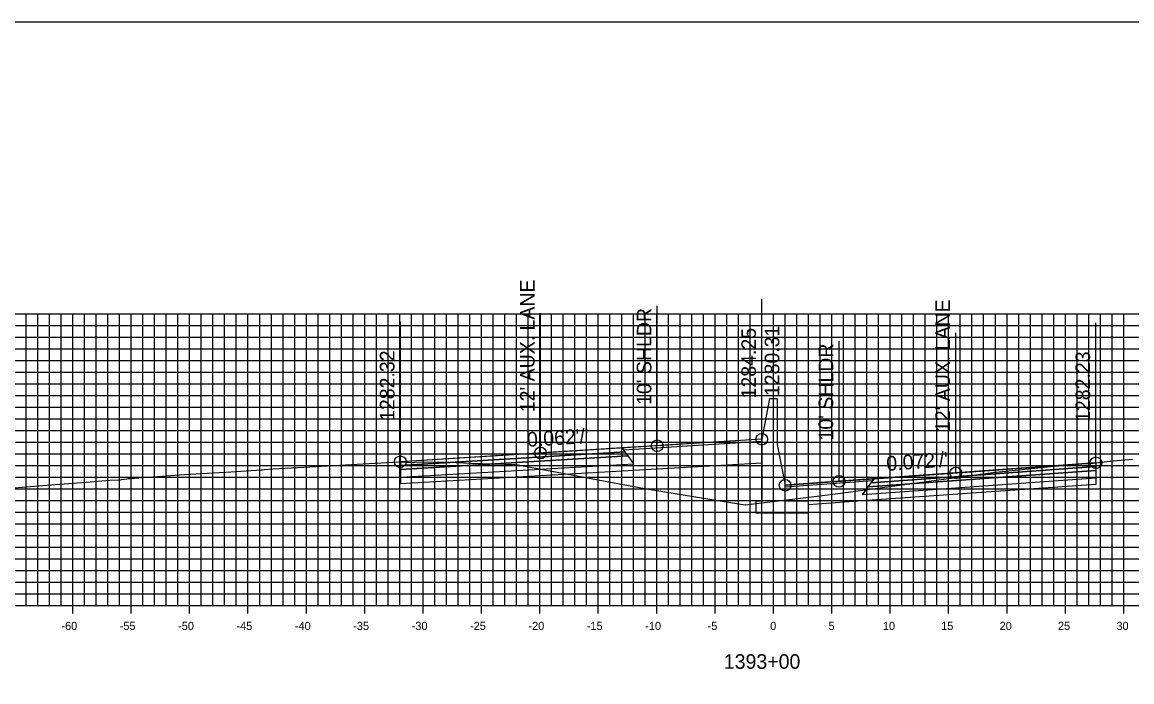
# Model space of a CAD drawing. Extents: x 674939 to 678919, y 750652 to 765176.
# Drawn here: x 678674.2 to 678769.2, y 755916 to 755972.6 of the extents above; entities that cross this region are included whole.
import ezdxf

# ---------------------------------------------------------------- set-up
doc = ezdxf.new("R2010")
doc.units = 0
for name, color, linetype in [('R_Alt Surface', 7, 'Continuous'), ('R_Axis', 7, 'Continuous'), ('R_Axis Annot', 7, 'Continuous'), ('R_Exist Surface', 7, 'Continuous'), ('R_Fin Surface', 7, 'Continuous'), ('R_Grid', 7, 'Continuous'), ('R_No Plot', 7, 'Continuous'), ('R_Proposed Road', 7, 'Continuous'), ('R_Xsect Elev', 7, 'Continuous'), ('R_Xsect Slope', 7, 'Continuous')]:
    doc.layers.add(name, color=color, linetype=linetype)

msp = doc.modelspace()

# ---------------------------------------------------------------- linework, layer by layer
at = {"layer": 'R_Alt Surface'}
for points in [[(678706.579, 755934.541), (678706.579, 755934.211), (678726.079, 755935.375), (678725.829, 755935.715)], [(678706.579, 755934.211), (678706.579, 755933.551), (678726.579, 755934.695), (678726.079, 755935.375)], [(678766.148, 755934.453), (678766.148, 755934.123), (678746.648, 755932.73), (678746.898, 755933.07)], [(678766.148, 755934.123), (678766.148, 755933.463), (678746.148, 755932.05), (678746.648, 755932.73)]]:
    msp.add_lwpolyline(points, close=True, dxfattribs=at)
for points in [[(678726.579, 755934.155), (678737.533, 755934.781)], [(678706.579, 755933.551), (678706.579, 755933.011), (678726.579, 755934.155)], [(678766.148, 755933.463), (678766.149, 755932.923), (678746.148, 755931.51)], [(678746.148, 755931.51), (678741.533, 755931.184)]]:
    msp.add_lwpolyline(points, dxfattribs=at)
at = {"layer": 'R_Axis'}
for p, q in [((678678.533, 755921.851), (678678.533, 755923.251)), ((678683.533, 755921.851), (678683.533, 755923.251)), ((678688.533, 755921.851), (678688.533, 755923.251)), ((678693.533, 755921.851), (678693.533, 755923.251)), ((678698.533, 755921.851), (678698.533, 755923.251)), ((678703.533, 755921.851), (678703.533, 755923.251)), ((678708.533, 755921.851), (678708.533, 755923.251)), ((678713.533, 755921.851), (678713.533, 755923.251)), ((678718.533, 755921.851), (678718.533, 755923.251)), ((678723.533, 755921.851), (678723.533, 755923.251)), ((678728.533, 755921.851), (678728.533, 755923.251)), ((678733.533, 755921.851), (678733.533, 755923.251)), ((678738.533, 755921.851), (678738.533, 755923.251)), ((678743.533, 755921.851), (678743.533, 755923.251)), ((678748.533, 755921.851), (678748.533, 755923.251)), ((678753.533, 755921.851), (678753.533, 755923.251)), ((678758.533, 755921.851), (678758.533, 755923.251)), ((678763.533, 755921.851), (678763.533, 755923.251)), ((678768.533, 755921.851), (678768.533, 755923.251)), ((678638.533, 755922.551), (678838.533, 755922.551))]:
    msp.add_line(p, q, dxfattribs=at)
at = {"layer": 'R_Exist Surface'}
msp.add_lwpolyline([(678673.502, 755932.632), (678674.889, 755932.752), (678678.883, 755933.066), (678679.678, 755933.126), (678681.363, 755933.259), (678681.693, 755933.282), (678682.61, 755933.327), (678682.691, 755933.337), (678683.169, 755933.412), (678683.277, 755933.425), (678683.41, 755933.445), (678686.155, 755933.63), (678687.631, 755933.737), (678690.522, 755933.921), (678691.628, 755933.986), (678694.665, 755934.172), (678694.762, 755934.178), (678694.908, 755934.195), (678695.666, 755934.259), (678698.302, 755934.407), (678706.462, 755934.868), (678706.555, 755934.872), (678706.579, 755934.871), (678706.585, 755934.871), (678706.834, 755934.858), (678707.562, 755934.821), (678707.761, 755934.822), (678707.861, 755934.831), (678709.212, 755934.851), (678709.663, 755934.845), (678710.711, 755934.824), (678710.745, 755934.829), (678712.622, 755934.764), (678716.508, 755934.628), (678722.598, 755933.482), (678727.475, 755932.569), (678733.415, 755931.596), (678736.095, 755931.177), (678742.501, 755931.962), (678744.928, 755932.251), (678750.814, 755933.056), (678757.324, 755933.954), (678760.64, 755934.289), (678762.55, 755934.494), (678762.599, 755934.487), (678763.64, 755934.591), (678764.256, 755934.64), (678765.296, 755934.708), (678765.502, 755934.725), (678765.65, 755934.721), (678765.74, 755934.731), (678766.148, 755934.783), (678767.074, 755934.902), (678767.658, 755934.964), (678769.285, 755935.096)], dxfattribs=at)
at = {"layer": 'R_Fin Surface'}
for points in [[(678737.533, 755936.8), (678728.579, 755936.242), (678718.579, 755935.619), (678706.579, 755934.871)], [(678766.148, 755934.783), (678754.148, 755933.916), (678744.148, 755933.194), (678739.533, 755932.86)]]:
    msp.add_lwpolyline(points, dxfattribs=at)
for points in [[(678725.697, 755935.895), (678737.533, 755936.64), (678737.533, 755936.8), (678725.579, 755936.055)], [(678706.579, 755934.871), (678706.579, 755934.541), (678725.829, 755935.715), (678725.579, 755936.055)], [(678766.148, 755934.783), (678766.148, 755934.453), (678746.898, 755933.07), (678747.148, 755933.41)], [(678747.03, 755933.25), (678739.533, 755932.7), (678739.533, 755932.86), (678747.148, 755933.41)]]:
    msp.add_lwpolyline(points, close=True, dxfattribs=at)
at = {"layer": 'R_Grid'}
for p, q in [((678638.533, 755947.551), (678838.533, 755947.551)), ((678674.533, 755922.551), (678674.533, 755947.551)), ((678675.533, 755922.551), (678675.533, 755947.551)), ((678676.533, 755922.551), (678676.533, 755947.551)), ((678677.533, 755922.551), (678677.533, 755947.551)), ((678678.533, 755922.551), (678678.533, 755947.551)), ((678679.533, 755922.551), (678679.533, 755947.551)), ((678680.533, 755922.551), (678680.533, 755947.551)), ((678681.533, 755922.551), (678681.533, 755947.551)), ((678682.533, 755922.551), (678682.533, 755947.551)), ((678683.533, 755922.551), (678683.533, 755947.551)), ((678684.533, 755922.551), (678684.533, 755947.551)), ((678685.533, 755922.551), (678685.533, 755947.551)), ((678686.533, 755922.551), (678686.533, 755947.551)), ((678687.533, 755922.551), (678687.533, 755947.551)), ((678688.533, 755922.551), (678688.533, 755947.551)), ((678689.533, 755922.551), (678689.533, 755947.551)), ((678690.533, 755922.551), (678690.533, 755947.551)), ((678691.533, 755922.551), (678691.533, 755947.551)), ((678692.533, 755922.551), (678692.533, 755947.551)), ((678693.533, 755922.551), (678693.533, 755947.551)), ((678694.533, 755922.551), (678694.533, 755947.551)), ((678695.533, 755922.551), (678695.533, 755947.551)), ((678696.533, 755922.551), (678696.533, 755947.551)), ((678697.533, 755922.551), (678697.533, 755947.551)), ((678698.533, 755922.551), (678698.533, 755947.551)), ((678699.533, 755922.551), (678699.533, 755947.551)), ((678700.533, 755922.551), (678700.533, 755947.551)), ((678701.533, 755922.551), (678701.533, 755947.551)), ((678702.533, 755922.551), (678702.533, 755947.551)), ((678703.533, 755922.551), (678703.533, 755947.551)), ((678704.533, 755922.551), (678704.533, 755947.551)), ((678705.533, 755922.551), (678705.533, 755947.551)), ((678706.533, 755922.551), (678706.533, 755947.551)), ((678707.533, 755922.551), (678707.533, 755947.551)), ((678708.533, 755922.551), (678708.533, 755947.551)), ((678709.533, 755922.551), (678709.533, 755947.551)), ((678710.533, 755922.551), (678710.533, 755947.551)), ((678711.533, 755922.551), (678711.533, 755947.551)), ((678712.533, 755922.551), (678712.533, 755947.551)), ((678713.533, 755922.551), (678713.533, 755947.551)), ((678714.533, 755922.551), (678714.533, 755947.551)), ((678715.533, 755922.551), (678715.533, 755947.551)), ((678716.533, 755922.551), (678716.533, 755947.551)), ((678717.533, 755922.551), (678717.533, 755947.551)), ((678718.533, 755922.551), (678718.533, 755947.551)), ((678719.533, 755922.551), (678719.533, 755947.551)), ((678720.533, 755922.551), (678720.533, 755947.551)), ((678721.533, 755922.551), (678721.533, 755947.551)), ((678722.533, 755922.551), (678722.533, 755947.551)), ((678723.533, 755922.551), (678723.533, 755947.551)), ((678724.533, 755922.551), (678724.533, 755947.551)), ((678725.533, 755922.551), (678725.533, 755947.551)), ((678726.533, 755922.551), (678726.533, 755947.551)), ((678727.533, 755922.551), (678727.533, 755947.551)), ((678728.533, 755922.551), (678728.533, 755947.551)), ((678729.533, 755922.551), (678729.533, 755947.551)), ((678730.533, 755922.551), (678730.533, 755947.551)), ((678731.533, 755922.551), (678731.533, 755947.551)), ((678732.533, 755922.551), (678732.533, 755947.551)), ((678733.533, 755922.551), (678733.533, 755947.551)), ((678734.533, 755922.551), (678734.533, 755947.551)), ((678735.533, 755922.551), (678735.533, 755947.551)), ((678736.533, 755922.551), (678736.533, 755947.551)), ((678737.533, 755922.551), (678737.533, 755947.551)), ((678738.533, 755922.551), (678738.533, 755947.551)), ((678739.533, 755922.551), (678739.533, 755947.551)), ((678740.533, 755922.551), (678740.533, 755947.551)), ((678741.533, 755922.551), (678741.533, 755947.551)), ((678742.533, 755922.551), (678742.533, 755947.551)), ((678743.533, 755922.551), (678743.533, 755947.551)), ((678744.533, 755922.551), (678744.533, 755947.551)), ((678745.533, 755922.551), (678745.533, 755947.551)), ((678746.533, 755922.551), (678746.533, 755947.551)), ((678747.533, 755922.551), (678747.533, 755947.551)), ((678748.533, 755922.551), (678748.533, 755947.551)), ((678749.533, 755922.551), (678749.533, 755947.551)), ((678750.533, 755922.551), (678750.533, 755947.551)), ((678751.533, 755922.551), (678751.533, 755947.551)), ((678752.533, 755922.551), (678752.533, 755947.551)), ((678753.533, 755922.551), (678753.533, 755947.551)), ((678754.533, 755922.551), (678754.533, 755947.551)), ((678755.533, 755922.551), (678755.533, 755947.551)), ((678756.533, 755922.551), (678756.533, 755947.551)), ((678757.533, 755922.551), (678757.533, 755947.551)), ((678758.533, 755922.551), (678758.533, 755947.551)), ((678759.533, 755922.551), (678759.533, 755947.551)), ((678760.533, 755922.551), (678760.533, 755947.551)), ((678761.533, 755922.551), (678761.533, 755947.551)), ((678762.533, 755922.551), (678762.533, 755947.551)), ((678763.533, 755922.551), (678763.533, 755947.551)), ((678764.533, 755922.551), (678764.533, 755947.551)), ((678765.533, 755922.551), (678765.533, 755947.551)), ((678766.533, 755922.551), (678766.533, 755947.551)), ((678767.533, 755922.551), (678767.533, 755947.551)), ((678768.533, 755922.551), (678768.533, 755947.551)), ((678638.533, 755946.551), (678838.533, 755946.551)), ((678638.533, 755945.551), (678838.533, 755945.551)), ((678638.533, 755944.551), (678838.533, 755944.551)), ((678638.533, 755943.551), (678838.533, 755943.551)), ((678638.533, 755942.551), (678838.533, 755942.551)), ((678638.533, 755941.551), (678838.533, 755941.551)), ((678638.533, 755940.551), (678838.533, 755940.551)), ((678638.533, 755939.551), (678838.533, 755939.551)), ((678638.533, 755938.551), (678838.533, 755938.551)), ((678638.533, 755937.551), (678838.533, 755937.551)), ((678638.533, 755936.551), (678838.533, 755936.551)), ((678638.533, 755935.551), (678838.533, 755935.551)), ((678638.533, 755934.551), (678838.533, 755934.551)), ((678638.533, 755933.551), (678838.533, 755933.551)), ((678638.533, 755932.551), (678838.533, 755932.551)), ((678638.533, 755931.551), (678838.533, 755931.551)), ((678638.533, 755930.551), (678838.533, 755930.551)), ((678638.533, 755929.551), (678838.533, 755929.551)), ((678638.533, 755928.551), (678838.533, 755928.551)), ((678638.533, 755927.551), (678838.533, 755927.551)), ((678638.533, 755926.551), (678838.533, 755926.551)), ((678638.533, 755925.551), (678838.533, 755925.551)), ((678638.533, 755924.551), (678838.533, 755924.551)), ((678638.533, 755923.551), (678838.533, 755923.551)), ((678638.533, 755922.551), (678838.533, 755922.551))]:
    msp.add_line(p, q, dxfattribs=at)
at = {"layer": 'R_No Plot'}
msp.add_lwpolyline([(678578.533, 755752.551), (678918.533, 755752.551), (678918.533, 755972.551), (678578.533, 755972.551)], close=True, dxfattribs=at)
for centre in [(678737.533, 755936.8), (678728.579, 755936.242), (678706.579, 755934.871), (678718.579, 755935.619), (678754.148, 755933.916), (678766.148, 755934.783), (678744.148, 755933.194), (678739.533, 755932.86)]:
    msp.add_circle(centre, 0.5, dxfattribs=at)
at = {"layer": 'R_Proposed Road'}
for points in [[(678738.203, 755940.3), (678737.533, 755936.8)], [(678738.203, 755940.3), (678738.203, 755940.3)], [(678738.203, 755940.3), (678738.863, 755940.3)], [(678738.863, 755940.3), (678738.863, 755936.36)], [(678737.533, 755936.8), (678737.533, 755931.485), (678737.033, 755931.485), (678737.033, 755930.485), (678741.533, 755930.485), (678741.533, 755931.485), (678739.533, 755931.485), (678739.533, 755932.86)], [(678738.863, 755936.36), (678739.533, 755932.86)]]:
    msp.add_lwpolyline(points, dxfattribs=at)
at = {"layer": 'R_Xsect Elev'}
for p, q in [((678737.533, 755936.8), (678737.533, 755948.8)), ((678728.579, 755936.242), (678728.579, 755948.242)), ((678706.579, 755934.871), (678706.579, 755946.871)), ((678718.579, 755935.619), (678718.579, 755947.619)), ((678766.148, 755934.783), (678766.148, 755946.783)), ((678754.148, 755933.916), (678754.148, 755945.916)), ((678744.148, 755933.194), (678744.148, 755945.194)), ((678739.533, 755932.86), (678739.533, 755944.86))]:
    msp.add_line(p, q, dxfattribs=at)

# ---------------------------------------------------------------- texts
at = {"layer": 'R_Axis Annot'}
for s, height, p in [('-60', 0.7, (678677.552, 755920.451)), ('-55', 0.7, (678682.546, 755920.451)), ('-50', 0.7, (678687.552, 755920.451)), ('-45', 0.7, (678692.546, 755920.451)), ('-40', 0.7, (678697.552, 755920.451)), ('-35', 0.7, (678702.546, 755920.451)), ('-30', 0.7, (678707.552, 755920.451)), ('-25', 0.7, (678712.546, 755920.451)), ('-20', 0.7, (678717.552, 755920.451)), ('-15', 0.7, (678722.546, 755920.451)), ('-10', 0.7, (678727.552, 755920.451)), ('-5', 0.7, (678732.896, 755920.451)), ('0', 0.7, (678738.252, 755920.451)), ('5', 0.7, (678743.246, 755920.451)), ('10', 0.7, (678747.902, 755920.451)), ('15', 0.7, (678752.896, 755920.451)), ('20', 0.7, (678757.902, 755920.451)), ('25', 0.7, (678762.896, 755920.451)), ('30', 0.7, (678767.902, 755920.451)), ('1393+00', 1.25, (678734.281, 755917.126))]:
    msp.add_text(s, height=height, dxfattribs=at).set_placement(p)
at = {"layer": 'R_Xsect Elev'}
for s, p in [("12' AUX. LANE", (678718.079, 755939.119)), ("12' AUX. LANE", (678753.648, 755937.416)), ("10' SHLDR", (678728.079, 755939.742)), ('1284.25', (678737.033, 755940.3)), ('1280.31', (678739.033, 755940.498)), ("10' SHLDR", (678743.648, 755936.694)), ('1282.32', (678706.079, 755938.371)), ('1282.23', (678765.648, 755938.283))]:
    msp.add_text(s, height=1.25, rotation=90, dxfattribs=at).set_placement(p)
at = {"layer": 'R_Xsect Slope'}
for s, rotation, p in [("0.062'/'", 3.5656, (678717.465, 755936.15)), ("0.072'/'", 4.13271, (678748.246, 755934.091))]:
    msp.add_text(s, height=1.25, rotation=rotation, dxfattribs=at).set_placement(p)

doc.saveas('drawing.dxf')
